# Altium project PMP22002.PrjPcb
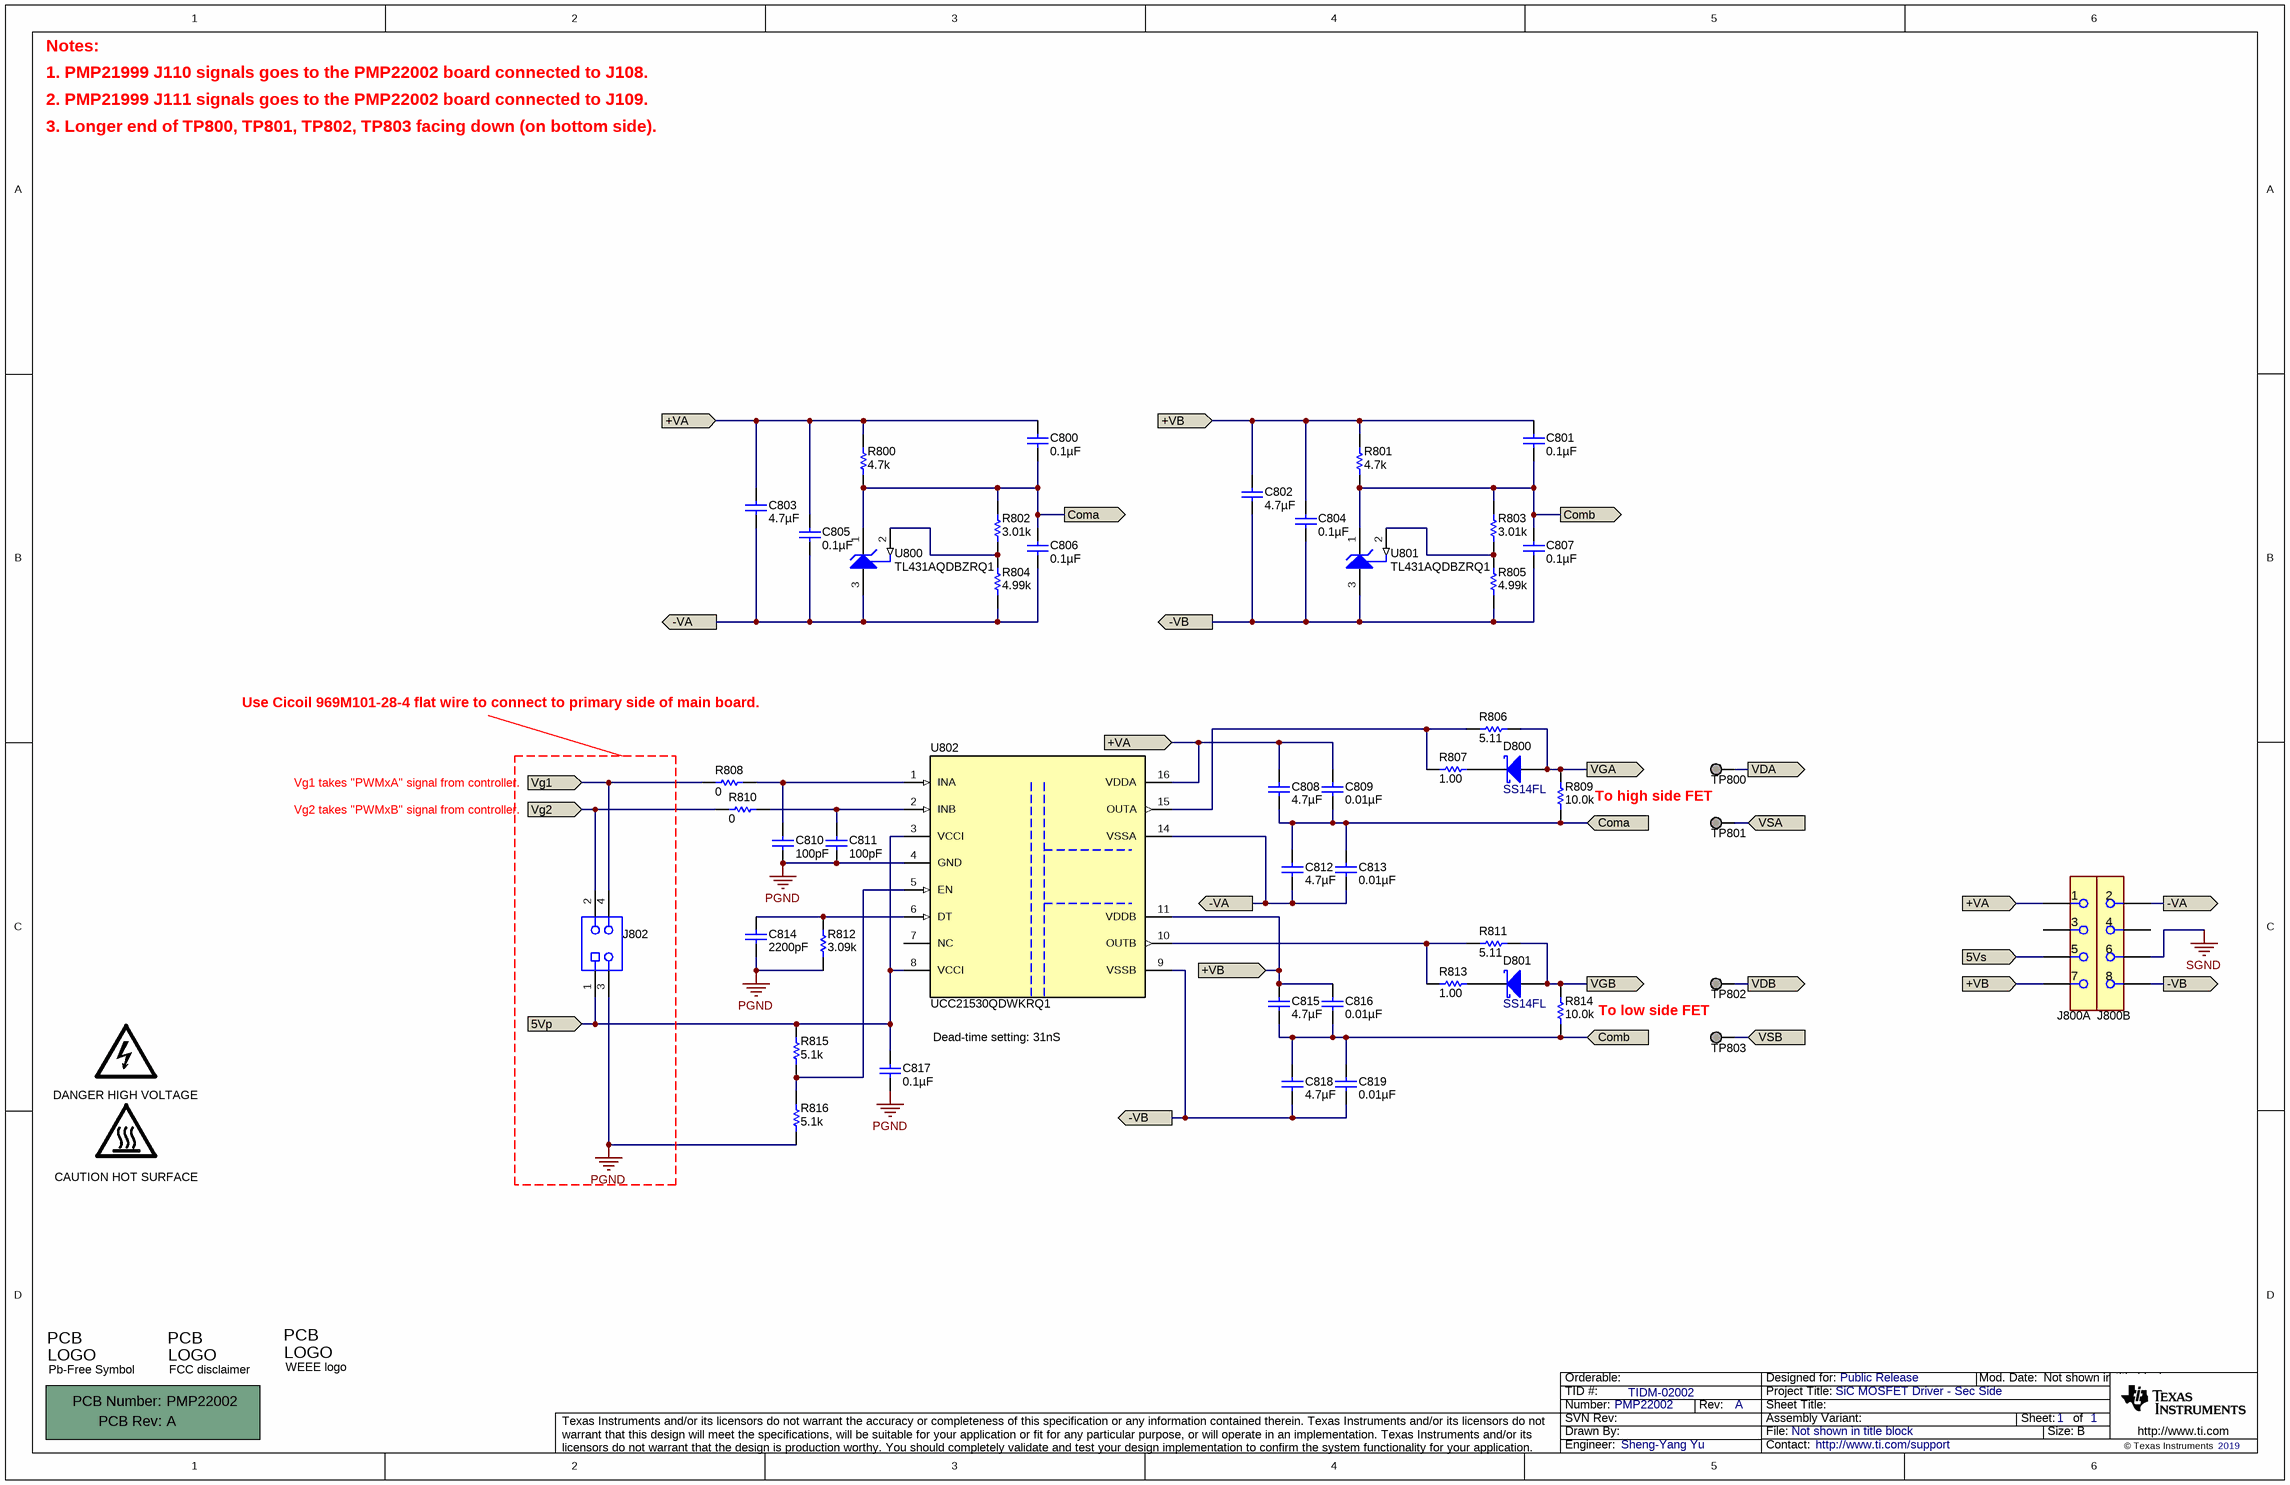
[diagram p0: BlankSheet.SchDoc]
CopyrightYear: 2019; PCB_Layout: Sheng-Yang Yu; PCB_Rev: A; PRJ_Customer: Public Release; PRJ_Engineer: Sheng-Yang Yu; PRJ_Number: PMP22002; PRJ_Title: SiC MOSFET Driver - Sec Side; SCH_Rev: A; TechSupport: http://www.ti.com/support; TID: TIDM-02002
1 sheet, 54 parts. Net scope: flat (ports and power ports of the same name join across sheets).
Board file: PCB.PcbDoc

## Sheet BlankSheet.SchDoc
size 431 x 279 mm; Date: Not shown in title block; ApprovedBy: Not shown in title block; CheckedBy: Not shown in title block; Author: Not shown in title block; CompanyName: Not shown in title block; Engineer: Not shown in title block; Organization: Not shown in title block; Address1: Not shown in title block; Address2: Not shown in title block; Address3: Not shown in title block; Address4: Not shown in title block; DocumentNumber: 1; Revision: Use project parameter SCH_Rev; SheetNumber: 1; SheetTotal: 1; PageSetup: Record=PageOptions¦CenterHorizontal=True¦CenterVertical=True¦PrintScale=1.00¦XCorrection=1.00¦YCorrection=1.00¦PrintKind=0¦BorderSize=5000000¦LeftOffset=0¦BottomOffset=0¦Orientation=2¦PaperLength=1000¦PaperWidth=1000¦Scale=100¦PaperSource=15¦PrintQuality=600¦MediaType=1¦DitherType=10¦PaperKind=Letter¦PrintScaleMode=1

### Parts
!PCB800  Printed Circuit Board  (value not drawn)  (mechanical)
C800  ValueDisplayed: 0.1µF  [0402]  (hidden comment: C1005X7R1H104K050BB)
C801  ValueDisplayed: 0.1µF  [0402]  (hidden comment: C1005X7R1H104K050BB)
C802  ValueDisplayed: 4.7µF  [0805_HV]  (hidden comment: CGA4J3X5R1H475K125AB)
C803  ValueDisplayed: 4.7µF  [0805_HV]  (hidden comment: CGA4J3X5R1H475K125AB)
C804  ValueDisplayed: 0.1µF  [0402]  (hidden comment: C1005X7R1H104K050BB)
C805  ValueDisplayed: 0.1µF  [0402]  (hidden comment: C1005X7R1H104K050BB)
C806  ValueDisplayed: 0.1µF  [0402]  (hidden comment: C1005X7R1H104K050BB)
C807  ValueDisplayed: 0.1µF  [0402]  (hidden comment: C1005X7R1H104K050BB)
C808  ValueDisplayed: 4.7µF  [0805_HV]  (hidden comment: CGA4J3X5R1H475K125AB)
C809  ValueDisplayed: 0.01µF  [0402]  (hidden comment: GRM155R71H103KA88D)
C810  ValueDisplayed: 100pF  [0402]  (hidden comment: 0402YC101KAT2A)
C811  ValueDisplayed: 100pF  [0402]  (hidden comment: 0402YC101KAT2A)
C812  ValueDisplayed: 4.7µF  [0805_HV]  (hidden comment: CGA4J3X5R1H475K125AB)
C813  ValueDisplayed: 0.01µF  [0402]  (hidden comment: GRM155R71H103KA88D)
C814  ValueDisplayed: 2200pF  [0402]  (hidden comment: 885012205027)
C815  ValueDisplayed: 4.7µF  [0805_HV]  (hidden comment: CGA4J3X5R1H475K125AB)
C816  ValueDisplayed: 0.01µF  [0402]  (hidden comment: GRM155R71H103KA88D)
C817  ValueDisplayed: 0.1µF  [0402]  (hidden comment: 0402YC104KAT2A)
C818  ValueDisplayed: 4.7µF  [0805_HV]  (hidden comment: CGA4J3X5R1H475K125AB)
C819  ValueDisplayed: 0.01µF  [0402]  (hidden comment: GRM155R71H103KA88D)
D800  SS14FL  [SOD-123F]
D801  SS14FL  [SOD-123F]
J800  CLT-104-02-G-D  [FP-CLT-104-02-G-D_HDR8-MFG]  (value not drawn)  (parts A,B of 2)
J802  CLT-102-02-G-D-BE  [Samtec_CLT-102-02-x-D-BE]  (value not drawn)
LOGO800  DANGER HIGH VOLTAGE  [IEC_HighVoltage_Small]  (no BOM)
LOGO804  CAUTION HOT SURFACE  [IEC_HotSurface_Small]  (no BOM)
Logo807  WEEE logo  [WEEE_Minimum]  (no BOM)
Logo808  Pb-Free Symbol  [Pb-Free_Overlay_Small]  (no BOM)
Logo809  FCC disclaimer  [FCC_disclaimer]  (no BOM)
R800  ValueDisplayed: 4.7k  [0805_HV]  (hidden comment: AC0805JR-074K7L)
R801  ValueDisplayed: 4.7k  [0805_HV]  (hidden comment: AC0805JR-074K7L)
R802  ValueDisplayed: 3.01k  [0402]  (hidden comment: CRCW04023K01FKED)
R803  ValueDisplayed: 3.01k  [0402]  (hidden comment: CRCW04023K01FKED)
R804  ValueDisplayed: 4.99k  [0402]  (hidden comment: CRCW04024K99FKED)
R805  ValueDisplayed: 4.99k  [0402]  (hidden comment: CRCW04024K99FKED)
R806  ValueDisplayed: 5.11  [0603]  (hidden comment: CRCW06035R11FKEA)
R807  ValueDisplayed: 1.00  [0603]  (hidden comment: RC0603FR-071RL)
R808  ValueDisplayed: 0  [0402]  (hidden comment: CRCW04020000Z0ED)
R809  ValueDisplayed: 10.0k  [0603]  (hidden comment: CRCW060310K0FKEA)
R810  ValueDisplayed: 0  [0402]  (hidden comment: CRCW04020000Z0ED)
R811  ValueDisplayed: 5.11  [0603]  (hidden comment: CRCW06035R11FKEA)
R812  ValueDisplayed: 3.09k  [0402]  (hidden comment: CRCW04023K09FKED)
R813  ValueDisplayed: 1.00  [0603]  (hidden comment: RC0603FR-071RL)
R814  ValueDisplayed: 10.0k  [0603]  (hidden comment: CRCW060310K0FKEA)
R815  ValueDisplayed: 5.1k  [0402]  (hidden comment: CRCW04025K10JNED)
R816  ValueDisplayed: 5.1k  [0402]  (hidden comment: CRCW04025K10JNED)
TP800  3104-2-00-34-00-00-08-0  [3104-2]  (value not drawn)
TP801  3104-2-00-34-00-00-08-0  [3104-2]  (value not drawn)
TP802  3104-2-00-34-00-00-08-0  [3104-2]  (value not drawn)
TP803  3104-2-00-34-00-00-08-0  [3104-2]  (value not drawn)
U800  TL431AQDBZRQ1  [DBZ0003A_N]
U801  TL431AQDBZRQ1  [DBZ0003A_N]
U802  UCC21530QDWKRQ1  [DWK0014A]

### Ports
5Vp (in), 5Vs (in), +VA (in), +VB (in), -VA (out), -VB (out), Coma (in), Coma (out), Comb (in), Comb (out), VDA (out), VDB (out), Vg1 (in), Vg2 (in), VGA (out), VGB (out), VSA (in), VSB (in)

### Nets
PGND: C810.2 C811.2 C814.2 C817.2 J802.3 R812.1 R816.1 U802.4(GND)
SGND: J800.6
5Vp: C817.1 J802.1 R815.2 U802.3(VCCI) U802.8(VCCI) ; port 5Vp
5Vs: J800.5 ; port 5Vs
+VA: C800.1 C803.1 C805.1 C808.1 C809.1 J800.1 R800.2 U802.16(VDDA) ; port +VA
+VB: C801.1 C802.1 C804.1 C815.1 C816.1 J800.7 R801.2 U802.11(VDDB) ; port +VB
-VA: C803.2 C805.2 C806.2 C812.2 C813.2 J800.2 R804.1 U800.3(ANODE) U802.14(VSSA) ; port -VA
-VB: C802.2 C804.2 C807.2 C818.2 C819.2 J800.8 R805.1 U801.3(ANODE) U802.9(VSSB) ; port -VB
Coma: C800.2 C806.1 C808.2 C809.2 C812.1 C813.1 R800.1 R802.2 R809.1 U800.1(CATHODE) ; port Coma
Comb: C801.2 C807.1 C815.2 C816.2 C818.1 C819.1 R801.1 R803.2 R814.1 U801.1(CATHODE) ; port Comb
VDA: TP800.1 ; port VDA
VDB: TP802.1 ; port VDB
Vg1: J802.4 R808.1 ; port Vg1
Vg2: J802.2 R810.1 ; port Vg2
VGA: D800.2(A) R806.2 R809.2 ; port VGA
VGB: D801.2(A) R811.2 R814.2 ; port VGB
VSA: TP801.1 ; port VSA
VSB: TP803.1 ; port VSB
NetC810_1: C810.1 R808.2 U802.1(INA)
NetC811_1: C811.1 R810.2 U802.2(INB)
NetC814_1: C814.1 R812.2 U802.6(DT)
NetD800_1: D800.1(K) R807.2
NetD801_1: D801.1(K) R813.2
NetR802_1: R802.1 R804.2 U800.2(REF)
NetR803_1: R803.1 R805.2 U801.2(REF)
NetR806_1: R806.1 R807.1 U802.15(OUTA)
NetR811_1: R811.1 R813.1 U802.10(OUTB)
NetR815_1: R815.1 R816.2 U802.5(EN)

Not connected (* = marked no-connect by the designer): J800 3 4; U802 7(NC)

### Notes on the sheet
- Notes:
- 1. PMP21999 J110 signals goes to the PMP22002 board connected to J108.
- 2. PMP21999 J111 signals goes to the PMP22002 board connected to J109.
- 3. Longer end of TP800, TP801, TP802, TP803 facing down (on bottom side).
- Use Cicoil 969M101-28-4 flat wire to connect to primary side of main board.
- Vg1 takes "PWMxA" signal from controller.
- Vg2 takes "PWMxB" signal from controller.
- To high side FET
- Dead-time setting: 31nS
- To low side FET

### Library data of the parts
!PCB800 = CMP-0003618-2: Manufacturer: Any; PartNumber: PMP22002
C800 C801 C804-C807 = C1005X7R1H104K050BB: CAP, CERM, 0.1 µF, 50 V,+/- 10%, X7R, 0402; Manufacturer: TDK; Polarized: N; CompType: Capacitor; Value: 0.1uF; U/M: EA; Cap_F: 0.0000001; Tolerance_%: 10; ESR_ohm: 0.039064; Value1: 0.039064 ohm; VDC_V: 50; Value2: 50V; IRMS_A: 0.814669; TaMin_C: -55; TaMax_C: 125; SizeArea_mm2: 0.5; SizeAreaWB_mm2: 3; SizeX_mm: 1; SizeZ_mm: 0.6; AEC Category: Q200; Green_Lifecycle: NRND; Green_REACh: Passed
C802 C803 C808 C812 C815 C818 = GRT21BR61H475KE13L: CAP, CERM, 4.7 µF, 50 V,+/- 10%, X5R, AEC-Q200 Grade 3, 0805; Manufacturer: TDK; Polarized: N; CompType: Capacitor; Value: 4.7uF; U/M: EA; Cap_F: 0.0000047; Tolerance_%: 10; VDC_V: 50; Value2: 50V; TaMin_C: -55; TaMax_C: 85; Cap_Case: 0805; SizeArea_mm2: 2.5; SizeAreaWB_mm2: 6.75; SizeX_mm: 2; SizeY_mm: 1.25; SizeZ_mm: 1.45; AEC Category: Q200; AEC Qualified: Y; AEC Grade: 3
C809 C813 C816 C819 = GRM155R71H103KA88D: CAP, CERM, 0.01 µF, 50 V,+/- 10%, X7R, 0402; Manufacturer: MuRata; Polarized: N; CompType: Capacitor; Value: 0.01uF; U/M: EA; Cap_F: 0.00000001; Tolerance_%: 10; VDC_V: 50; Value2: 50V; TaMin_C: -55; TaMax_C: 125; SizeArea_mm2: 0.5; SizeAreaWB_mm2: 3; SizeX_mm: 1; SizeZ_mm: 0.6; AEC Category: Q200; Green_Lifecycle: Active; Green_REACh: Passed
C810 C811 = 0402YC101KAT2A: CAP, CERM, 100 pF, 16 V,+/- 10%, X7R, 0402; Manufacturer: AVX; Polarized: N; CompType: Capacitor; Value: 100pF; U/M: EA; Cap_F: 0.0000000001; Tolerance_%: 10; VDC_V: 16; Value2: 16V; TaMin_C: -55; TaMax_C: 125; SizeArea_mm2: 0.5; SizeAreaWB_mm2: 3; SizeX_mm: 1; SizeZ_mm: 0.6; AEC Category: Q200
C814 = 885012205027: CAP, CERM, 2200 pF, 16 V,+/- 10%, X7R, 0402; Manufacturer: Wurth Elektronik; Polarized: N; CompType: Capacitor; Value: 2200pF; U/M: EA; Cap_F: 0.0000000022; Tolerance_%: 10; VDC_V: 16; Value2: 16V; TaMin_C: -55; TaMax_C: 125; SizeArea_mm2: 0.5; SizeAreaWB_mm2: 3; SizeX_mm: 1; SizeZ_mm: 0.6; AEC Category: Q200
C817 = 0402YC104KAT2A: CAP, CERM, 0.1 µF, 16 V,+/- 10%, X7R, 0402; Manufacturer: AVX; Polarized: N; CompType: Capacitor; Value: 0.1uF; U/M: EA; Cap_F: 0.0000001; Tolerance_%: 10; VDC_V: 16; Value2: 16V; TaMin_C: -55; TaMax_C: 125; SizeArea_mm2: 0.5; SizeAreaWB_mm2: 3; SizeX_mm: 1; SizeZ_mm: 0.6; AEC Category: Q200; Green_Lifecycle: Active; Green_REACh: Passed
D800 D801 = CMP-0028801-2: Diode, Schottky, 40 V, 1 A, AEC-Q101, SOD-123F; Manufacturer: Fairchild Semiconductor; Value1: 1A; SizeX_mm: 3.5; Vr_V: 40V; Value2: 0.55V; AEC Category: Q101; Vf_V: 550mV; SizeArea_mm2: 5.6; SizeZ_mm: 1.1; Value: 40V; AEC Qualified: Y; SizeAreaWB_mm2: 11.7; SizeY_mm: 1.6; TJmax_C: 125°C; Green_REACh: Incomplete; Green_Lifecycle: Not Set
J800 = CMP-0086478-1: CONN RCPT 8POS 0.079 GOLD SMD; Manufacturer: Samtec; Row_Count: 2; ContactFinish: Gold,Nickel; Current_A: 4.1A; Symbol Name: SYM-CLT-104-02-G-D
J802 = CMP-0082275-1: Receptacle, 2mm, 2x2, Gold, SMT; Manufacturer: Samtec; Pitch_mm: 2; Gender: Female; Cert_UL: Y; Current_A: 4.1A; CompType: Socket Strip
LOGO800 = IEC_HighVoltage: IEC 61010-1 High Voltage Warning; SymbolCreator: a0412235
LOGO804 = IEC_HotSurface: IEC 61010-1 Hot Surface Warning; SymbolCreator: a0412235
Logo807 = CMP-0074769-1
Logo808 = CMP-0074839-1: SymbolCreator: a0412235; Library Reference: Logo
Logo809 = CMP-0074847-1: FCC_disclaimer; Library Reference: Logo
R800 R801 = CRCW08054K70JNEA: RES, 4.7 k, 5%, 0.125 W, 0805; Manufacturer: Yageo America; CompType: Resistor; Value: 4.7k; Res_ohm: 4700; Value_Code: 4k70; Tolerance_%: 5; Power_W: 0.125; Value2: 0.125W; VDC_V: 150; TempCo: 200 ppm/C; SizeArea_mm2: 2.5; SizeX_mm: 2; SizeY_mm: 1.25; SizeZ_mm: 1.45; EIA_Code: E24; U/M: EA; AEC Category: Q200; Green_Lifecycle: Active; Green_REACh: Passed
R802 R803 = CRCW04023K01FKED: RES, 3.01 k, 1%, 0.063 W, 0402; Manufacturer: Vishay-Dale; CompType: Resistor; Value: 3.01k; Res_ohm: 3010; Value_Code: 3k01; Tolerance_%: 1; Power_W: 0.063; Value2: 0.063W; VDC_V: 50; TempCo: 100 ppm/C; SizeArea_mm2: 0.5; SizeZ_mm: 0.6; EIA_Code: E96; U/M: EA; AEC Category: Q200; Green_Lifecycle: Active; Green_REACh: Passed
R804 R805 = CRCW04024K99FKED: RES, 4.99 k, 1%, 0.063 W, 0402; Manufacturer: Vishay-Dale; CompType: Resistor; Value: 4.99k; Res_ohm: 4990; Value_Code: 4k99; Tolerance_%: 1; Power_W: 0.063; Value2: 0.063W; VDC_V: 50; TempCo: 100 ppm/C; SizeArea_mm2: 0.5; SizeZ_mm: 0.6; EIA_Code: E96; U/M: EA; AEC Category: Q200; Green_Lifecycle: Active; Green_REACh: Passed
R806 R811 = CRCW06035R11FKEA: RES, 5.11, 1%, 0.1 W, 0603; Manufacturer: Vishay-Dale; CompType: Resistor; Value: 5.11; Value_Code: 5R11; Tolerance_%: 1; Power_W: 0.1; Value2: 0.1W; VDC_V: 75; TempCo: 100 ppm/C; SizeArea_mm2: 1.28; SizeX_mm: 1.6; SizeY_mm: 0.8; EIA_Code: E96; U/M: EA; AEC Category: Q200; Green_Lifecycle: Active; Green_REACh: Passed
R807 R813 = RC0603FR-071RL: RES, 1.00, 1%, 0.1 W, 0603; Manufacturer: Yageo America; CompType: Resistor; Value: 1.00; Res_ohm: 1; Value_Code: 1R00; Power_W: 0.1; Value2: 0.1W; VDC_V: 150; TempCo: 200 ppm/C; SizeArea_mm2: 1.28; SizeX_mm: 1.6; SizeY_mm: 0.8; EIA_Code: E96; U/M: EA; AEC Category: Q200; Green_Lifecycle: Active; Green_REACh: Passed
R808 R810 = CRCW04020000Z0ED: RES, 0, 5%, 0.063 W, 0402; Manufacturer: Vishay-Dale; CompType: Resistor; Value: 0; Value_Code: 0000; Tolerance_%: 5; Power_W: 0.063; Value2: 0.063W; VDC_V: 50; TempCo: 200 ppm/C; SizeArea_mm2: 0.5; SizeX_mm: 1; SizeZ_mm: 0.6; EIA_Code: E24; U/M: EA; AEC Category: Q200; Green_Lifecycle: Active; Green_REACh: Passed
R809 R814 = CRCW060310K0FKEA: RES, 10.0 k, 1%, 0.1 W, 0603; Manufacturer: Vishay-Dale; CompType: Resistor; Value: 10.0k; Res_ohm: 10000; Value_Code: 10k0; Tolerance_%: 1; Power_W: 0.1; Value2: 0.1W; VDC_V: 75; TempCo: 100 ppm/C; SizeArea_mm2: 1.28; SizeX_mm: 1.6; SizeY_mm: 0.8; EIA_Code: E96; U/M: EA; AEC Category: Q200; Green_Lifecycle: Active; Green_REACh: Passed
R812 = CRCW04023K09FKED: RES, 3.09 k, 1%, 0.063 W, 0402; Manufacturer: Vishay-Dale; CompType: Resistor; Value: 3.09k; Res_ohm: 3090; Value_Code: 3k09; Tolerance_%: 1; Power_W: 0.063; Value2: 0.063W; VDC_V: 50; TempCo: 100 ppm/C; SizeArea_mm2: 0.5; SizeZ_mm: 0.6; EIA_Code: E96; U/M: EA; AEC Category: Q200; Green_Lifecycle: Active; Green_REACh: Passed
R815 R816 = CRCW04025K10JNED: RES, 5.1 k, 5%, 0.063 W, 0402; Manufacturer: Vishay-Dale; CompType: Resistor; Value: 5.1k; Res_ohm: 5100; Value_Code: 5k10; Tolerance_%: 5; Power_W: 0.063; Value2: 0.063W; VDC_V: 50; TempCo: 200 ppm/C; SizeArea_mm2: 0.5; SizeX_mm: 1; SizeZ_mm: 0.6; EIA_Code: E24; U/M: EA; AEC Category: Q200; Green_Lifecycle: Active; Green_REACh: Passed
TP800-TP803 = CMP-0055001-1: PCB Pin, Swage Mount, TH; Manufacturer: Mill-Max; CNHeader: FALSE; Green_Lifecycle: Active; Green_REACh: Passed; CompType: PCB Pin
U800 U801 = TL431AQDBZRQ1: Automotive Catalog Adjustable Precision Shunt Regulator, 34 ppm / degC, 100 mA, -40 to 125 degC, 3-pin SOT-23 (DBZ), Green (RoHS & no Sb/Br); Manufacturer: Texas Instruments; Alternate PartNumber: Equivalent; Initial Accuracy @ 25/deg C(%): 1; Iout/Iz(Max)(mA): 100; Min Iz for Regulation(uA): 600; SubFamily: Shunt Voltage Reference; Temp Coeff(Typ)(ppm/ degree C): 34; VO Adj(Max)(V): 36; VO Adj(Min)(V): 2.495
U802 = CMP-0083997-1: 4-A, 6-A, 5.7-kVRMS Isolated Dual-Channel Gate Driver with Enable, DWK0014A (SOIC-14); Alternate PartNumber: UCC21530QDWKQ1; Alternate Manufacturer: Texas Instruments; SizeAreaWB_mm2: 151.29; SizeZ_mm: 2.65; SizeX_mm: 10.3; SizeArea_mm2: 106.09; CompType: IC; AEC Qualified: Y; AEC Category: Q200

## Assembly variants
001: all parts fitted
